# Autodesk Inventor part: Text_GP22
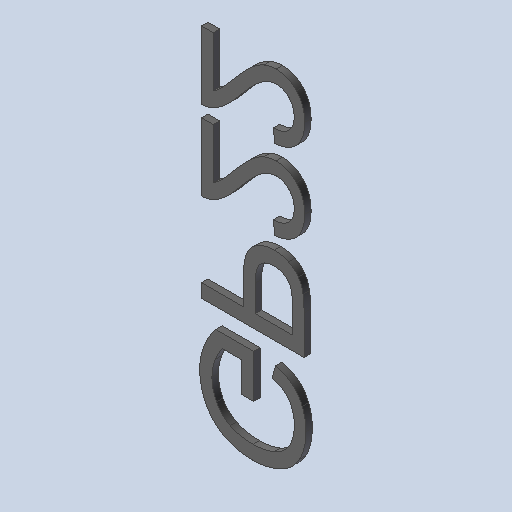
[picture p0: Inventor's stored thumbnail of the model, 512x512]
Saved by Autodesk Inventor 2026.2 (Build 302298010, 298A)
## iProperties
Created: 2026-10
Part Number: Text_GP22
Material: Générique
Document SubType Name: Modeling
Designer: mel
Density: 1 g/cm^3
Appearance: Par défaut
Author: mel
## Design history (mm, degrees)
feature "Base1"
feature "Base2"
feature "Base3"
feature "Base4"
node "Solide1"
node "Solide2"
node "Solide3"
node "Solide4"
